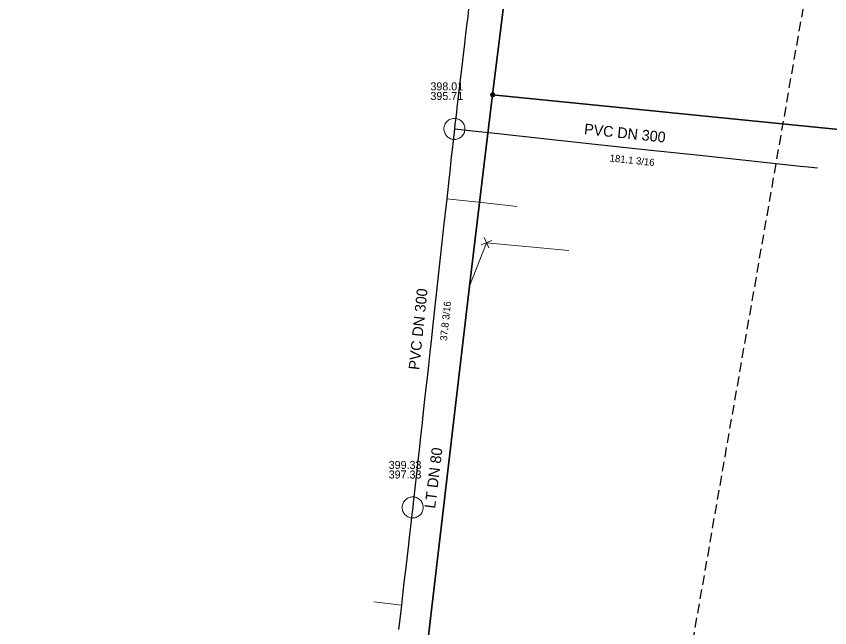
# Model space of a CAD drawing. Extents: x -772952 to -772403, y -1033777 to -1033210.
# Drawn here: x -772682 to -772590.6, y -1033571.6 to -1033502.9 of the extents above; entities that cross this region are included whole.
import ezdxf

# ---------------------------------------------------------------- set-up
doc = ezdxf.new("R2010")
doc.units = 0
doc.header["$LTSCALE"] = 0.36
doc.linetypes.add('MEDIUM_DASHED', pattern=[4.5, 3, -1.5])
for name, color, linetype, lineweight in [('15', 7, 'Continuous', 13), ('16', 7, 'Continuous', 35), ('2', 7, 'Continuous', 25), ('4', 7, 'Continuous', 13), ('57', 7, 'Continuous', 13), ('59', 7, 'Continuous', 13), ('62', 7, 'MEDIUM_DASHED', 25)]:
    doc.layers.add(name, color=color, linetype=linetype, lineweight=lineweight)
for name, color, linetype in [('17', 7, 'Continuous'), ('3', 7, 'Continuous'), ('6', 7, 'Continuous')]:
    doc.layers.add(name, color=color, linetype=linetype)

msp = doc.modelspace()

# ---------------------------------------------------------------- linework, layer by layer
at = {"layer": '15'}
for p, q in [((-772629.75, -1033528.584), (-772628.564, -1033528.075)), ((-772628.901, -1033528.926), (-772629.417, -1033527.731))]:
    msp.add_line(p, q, dxfattribs=at)
for points in [[(-772628.242, -1033511.706), (-772628.248, -1033511.654), (-772628.265, -1033511.604), (-772628.294, -1033511.56), (-772628.331, -1033511.523), (-772628.376, -1033511.496), (-772628.426, -1033511.479), (-772628.479, -1033511.475), (-772628.531, -1033511.482), (-772628.58, -1033511.501), (-772628.623, -1033511.53), (-772628.659, -1033511.569), (-772628.685, -1033511.614), (-772628.701, -1033511.665), (-772628.704, -1033511.717), (-772628.696, -1033511.769), (-772628.676, -1033511.818), (-772628.645, -1033511.861), (-772628.606, -1033511.895), (-772628.56, -1033511.921), (-772628.509, -1033511.935), (-772628.456, -1033511.937), (-772628.405, -1033511.927), (-772628.357, -1033511.906), (-772628.314, -1033511.875), (-772628.28, -1033511.834), (-772628.256, -1033511.788), (-772628.244, -1033511.737)], [(-772628.272, -1033511.706), (-772628.278, -1033511.657), (-772628.295, -1033511.611), (-772628.323, -1033511.571), (-772628.36, -1033511.539), (-772628.404, -1033511.517), (-772628.452, -1033511.506), (-772628.501, -1033511.506), (-772628.548, -1033511.519), (-772628.591, -1033511.543), (-772628.627, -1033511.576), (-772628.654, -1033511.617), (-772628.67, -1033511.664), (-772628.674, -1033511.713), (-772628.667, -1033511.761), (-772628.648, -1033511.806), (-772628.618, -1033511.846), (-772628.58, -1033511.877), (-772628.536, -1033511.897), (-772628.488, -1033511.907), (-772628.439, -1033511.905), (-772628.392, -1033511.89), (-772628.349, -1033511.865), (-772628.315, -1033511.831), (-772628.289, -1033511.789), (-772628.275, -1033511.742)], [(-772628.302, -1033511.706), (-772628.308, -1033511.661), (-772628.325, -1033511.619), (-772628.353, -1033511.584), (-772628.389, -1033511.557), (-772628.431, -1033511.54), (-772628.476, -1033511.535), (-772628.521, -1033511.541), (-772628.562, -1033511.56), (-772628.597, -1033511.588), (-772628.624, -1033511.625), (-772628.64, -1033511.667), (-772628.644, -1033511.712), (-772628.637, -1033511.757), (-772628.618, -1033511.798), (-772628.589, -1033511.832), (-772628.552, -1033511.858), (-772628.509, -1033511.874), (-772628.464, -1033511.877), (-772628.419, -1033511.869), (-772628.379, -1033511.849), (-772628.345, -1033511.82), (-772628.319, -1033511.782), (-772628.305, -1033511.739)], [(-772628.332, -1033511.706), (-772628.337, -1033511.665), (-772628.355, -1033511.628), (-772628.382, -1033511.597), (-772628.417, -1033511.576), (-772628.457, -1033511.565), (-772628.498, -1033511.567), (-772628.537, -1033511.58), (-772628.571, -1033511.604), (-772628.596, -1033511.636), (-772628.611, -1033511.674), (-772628.614, -1033511.715), (-772628.606, -1033511.755), (-772628.586, -1033511.791), (-772628.557, -1033511.82), (-772628.52, -1033511.839), (-772628.48, -1033511.847), (-772628.439, -1033511.843), (-772628.401, -1033511.828), (-772628.369, -1033511.802), (-772628.346, -1033511.768), (-772628.333, -1033511.729)], [(-772628.362, -1033511.706), (-772628.367, -1033511.67), (-772628.385, -1033511.638), (-772628.411, -1033511.613), (-772628.445, -1033511.598), (-772628.481, -1033511.595), (-772628.516, -1033511.603), (-772628.547, -1033511.623), (-772628.57, -1033511.651), (-772628.583, -1033511.685), (-772628.583, -1033511.722), (-772628.572, -1033511.757), (-772628.551, -1033511.786), (-772628.521, -1033511.807), (-772628.486, -1033511.817), (-772628.449, -1033511.815), (-772628.415, -1033511.801), (-772628.388, -1033511.778), (-772628.369, -1033511.746), (-772628.362, -1033511.711)], [(-772628.392, -1033511.706), (-772628.397, -1033511.675), (-772628.414, -1033511.649), (-772628.44, -1033511.632), (-772628.47, -1033511.625), (-772628.501, -1033511.629), (-772628.528, -1033511.646), (-772628.546, -1033511.67), (-772628.554, -1033511.701), (-772628.55, -1033511.731), (-772628.535, -1033511.759), (-772628.511, -1033511.778), (-772628.481, -1033511.787), (-772628.45, -1033511.784), (-772628.422, -1033511.77), (-772628.402, -1033511.746), (-772628.392, -1033511.717)], [(-772628.422, -1033511.706), (-772628.427, -1033511.682), (-772628.444, -1033511.664), (-772628.467, -1033511.655), (-772628.491, -1033511.658), (-772628.512, -1033511.672), (-772628.523, -1033511.694), (-772628.523, -1033511.719), (-772628.511, -1033511.74), (-772628.491, -1033511.754), (-772628.466, -1033511.757), (-772628.443, -1033511.748), (-772628.427, -1033511.73)], [(-772628.452, -1033511.706), (-772628.457, -1033511.691), (-772628.472, -1033511.685), (-772628.487, -1033511.689), (-772628.494, -1033511.703), (-772628.49, -1033511.718), (-772628.477, -1033511.727), (-772628.462, -1033511.724), (-772628.452, -1033511.712)]]:
    msp.add_lwpolyline(points, close=True, dxfattribs=at)
at = {"layer": '16'}
for points in [[(-772624.872, -1033476.41), (-772627.006, -1033499.655), (-772628.473, -1033511.706)], [(-772628.473, -1033511.706), (-772629.473, -1033519.771), (-772631.094, -1033533.208), (-772638.368, -1033595.513)], [(-772483.133, -1033521.096), (-772487.637, -1033525.287), (-772488.111, -1033525.728), (-772490.767, -1033526.46), (-772498.958, -1033525.679), (-772521.951, -1033523.03), (-772540.945, -1033520.877), (-772542.85, -1033520.681), (-772544.243, -1033520.513), (-772566.739, -1033518.022), (-772588.807, -1033515.688), (-772628.473, -1033511.706)]]:
    msp.add_lwpolyline(points, dxfattribs=at)
at = {"layer": '2'}
for points in [[(-772631.177, -1033502.011), (-772631.28, -1033502.885), (-772631.399, -1033503.898), (-772631.515, -1033504.884), (-772631.644, -1033505.981), (-772631.752, -1033506.894), (-772631.868, -1033507.884), (-772631.979, -1033508.826), (-772632.082, -1033509.698), (-772632.191, -1033510.628), (-772632.303, -1033511.579), (-772632.378, -1033512.215), (-772632.484, -1033513.114), (-772632.547, -1033513.653), (-772632.616, -1033514.235), (-772632.657, -1033514.587), (-772632.677, -1033514.751), (-772632.706, -1033514.999), (-772632.77, -1033515.54)], [(-772632.77, -1033515.54), (-772632.844, -1033516.218), (-772632.917, -1033516.881), (-772633.023, -1033517.843), (-772633.118, -1033518.701), (-772633.211, -1033519.548), (-772633.338, -1033520.695), (-772633.365, -1033520.945), (-772633.635, -1033523.392), (-772633.706, -1033524.036), (-772633.947, -1033526.225), (-772634.593, -1033532.066), (-772635.228, -1033537.849), (-772635.359, -1033539.043), (-772635.537, -1033540.656), (-772635.702, -1033542.147), (-772635.848, -1033543.473), (-772635.978, -1033544.654), (-772636.12, -1033545.947), (-772636.273, -1033547.335), (-772636.448, -1033548.921), (-772636.58, -1033550.117), (-772636.751, -1033551.669), (-772636.879, -1033552.83), (-772637.041, -1033554.3), (-772637.22, -1033555.926), (-772637.335, -1033556.97), (-772637.363, -1033557.226), (-772637.397, -1033557.536), (-772637.46, -1033558.1)], [(-772632.77, -1033515.54), (-772632.028, -1033515.619), (-772631.463, -1033515.68), (-772627.848, -1033516.068), (-772617.68, -1033517.16), (-772611.035, -1033517.873), (-772605.195, -1033518.5), (-772601.075, -1033518.943), (-772597.276, -1033519.353), (-772593.916, -1033519.712), (-772593.019, -1033519.808), (-772591.98, -1033519.92)], [(-772637.46, -1033558.1), (-772637.548, -1033558.859), (-772637.592, -1033559.242), (-772637.708, -1033560.238), (-772637.809, -1033561.105), (-772637.945, -1033562.275), (-772638.094, -1033563.551), (-772638.246, -1033564.861), (-772638.406, -1033566.236), (-772638.562, -1033567.582), (-772638.736, -1033569.078), (-772638.919, -1033570.648), (-772639.058, -1033571.841)]]:
    msp.add_lwpolyline(points, dxfattribs=at)
at = {"layer": '4'}
for points in [[(-772631.59, -1033515.54), (-772631.596, -1033515.421), (-772631.614, -1033515.304), (-772631.643, -1033515.188), (-772631.684, -1033515.077), (-772631.736, -1033514.97), (-772631.799, -1033514.869), (-772631.872, -1033514.774), (-772631.953, -1033514.688), (-772632.043, -1033514.61), (-772632.141, -1033514.541), (-772632.244, -1033514.483), (-772632.353, -1033514.436), (-772632.467, -1033514.399), (-772632.583, -1033514.374), (-772632.701, -1033514.362), (-772632.82, -1033514.361), (-772632.939, -1033514.372), (-772633.055, -1033514.395), (-772633.169, -1033514.429), (-772633.279, -1033514.475), (-772633.384, -1033514.532), (-772633.482, -1033514.599), (-772633.573, -1033514.675), (-772633.656, -1033514.76), (-772633.73, -1033514.854), (-772633.794, -1033514.954), (-772633.848, -1033515.06), (-772633.891, -1033515.171), (-772633.923, -1033515.285), (-772633.942, -1033515.403), (-772633.95, -1033515.522), (-772633.946, -1033515.64), (-772633.93, -1033515.758), (-772633.902, -1033515.874), (-772633.863, -1033515.986), (-772633.812, -1033516.094), (-772633.751, -1033516.196), (-772633.68, -1033516.292), (-772633.6, -1033516.379), (-772633.511, -1033516.459), (-772633.415, -1033516.529), (-772633.312, -1033516.589), (-772633.204, -1033516.638), (-772633.091, -1033516.676), (-772632.975, -1033516.702), (-772632.857, -1033516.717), (-772632.738, -1033516.72), (-772632.62, -1033516.711), (-772632.502, -1033516.69), (-772632.388, -1033516.657), (-772632.278, -1033516.613), (-772632.172, -1033516.558), (-772632.073, -1033516.492), (-772631.98, -1033516.417), (-772631.896, -1033516.333), (-772631.821, -1033516.241), (-772631.755, -1033516.142), (-772631.699, -1033516.037), (-772631.655, -1033515.927), (-772631.621, -1033515.813), (-772631.6, -1033515.696), (-772631.59, -1033515.577)], [(-772636.279, -1033558.1), (-772636.286, -1033557.981), (-772636.304, -1033557.864), (-772636.333, -1033557.748), (-772636.374, -1033557.637), (-772636.426, -1033557.53), (-772636.489, -1033557.429), (-772636.561, -1033557.334), (-772636.642, -1033557.248), (-772636.733, -1033557.17), (-772636.831, -1033557.101), (-772636.934, -1033557.043), (-772637.043, -1033556.996), (-772637.157, -1033556.959), (-772637.272, -1033556.934), (-772637.391, -1033556.922), (-772637.51, -1033556.921), (-772637.629, -1033556.932), (-772637.745, -1033556.955), (-772637.858, -1033556.989), (-772637.968, -1033557.035), (-772638.073, -1033557.092), (-772638.172, -1033557.159), (-772638.262, -1033557.235), (-772638.346, -1033557.32), (-772638.419, -1033557.414), (-772638.483, -1033557.514), (-772638.538, -1033557.62), (-772638.581, -1033557.731), (-772638.613, -1033557.845), (-772638.632, -1033557.963), (-772638.64, -1033558.082), (-772638.636, -1033558.2), (-772638.62, -1033558.318), (-772638.592, -1033558.434), (-772638.553, -1033558.546), (-772638.502, -1033558.654), (-772638.441, -1033558.756), (-772638.37, -1033558.852), (-772638.289, -1033558.939), (-772638.201, -1033559.019), (-772638.105, -1033559.089), (-772638.002, -1033559.149), (-772637.894, -1033559.198), (-772637.781, -1033559.236), (-772637.664, -1033559.262), (-772637.547, -1033559.277), (-772637.428, -1033559.28), (-772637.309, -1033559.271), (-772637.191, -1033559.25), (-772637.078, -1033559.217), (-772636.968, -1033559.173), (-772636.862, -1033559.118), (-772636.762, -1033559.052), (-772636.669, -1033558.977), (-772636.586, -1033558.893), (-772636.511, -1033558.801), (-772636.445, -1033558.702), (-772636.389, -1033558.597), (-772636.345, -1033558.487), (-772636.311, -1033558.373), (-772636.289, -1033558.256), (-772636.279, -1033558.137)]]:
    msp.add_lwpolyline(points, close=True, dxfattribs=at)
at = {"layer": '57'}
msp.add_line((-772638.736, -1033569.078), (-772641.84, -1033568.71), dxfattribs=at)
msp.add_lwpolyline([(-772633.635, -1033523.392), (-772629.024, -1033523.904), (-772625.76, -1033524.27)], dxfattribs=at)
at = {"layer": '59'}
msp.add_lwpolyline([(-772631.094, -1033533.209), (-772629.16, -1033528.33), (-772619.92, -1033529.22)], dxfattribs=at)
at = {"layer": '62'}
msp.add_lwpolyline([(-772641.514, -1033776.98), (-772641.529, -1033776.987), (-772951.708, -1033584.106), (-772846.395, -1033249.938), (-772562.451, -1033323.146)], close=True, dxfattribs=at)

# ---------------------------------------------------------------- texts
at = {"layer": '17'}
msp.add_text('LT DN 80', height=1.2, rotation=83, dxfattribs=at).set_placement((-772634.946, -1033558.262))
at = {"layer": '3'}
for s, height, rotation, p in [('PVC DN 300', 1.2, 354, (-772618.237, -1033516.122)), ('181.1 3/16 ', 0.8, 354, (-772615.347, -1033519.195)), ('PVC DN 300', 1.2, 84, (-772636.736, -1033542.676)), ('37.8 3/16', 0.8, 84, (-772633.611, -1033539.399))]:
    msp.add_text(s, height=height, rotation=rotation, dxfattribs=at).set_placement(p)
at = {"layer": '6'}
for s, p in [('398.01', (-772635.468, -1033511.208)), ('395.71', (-772635.468, -1033512.285)), ('399.33', (-772640.158, -1033553.767)), ('397.33', (-772640.158, -1033554.844))]:
    msp.add_text(s, height=0.9, dxfattribs=at).set_placement(p)

doc.saveas('drawing.dxf')
